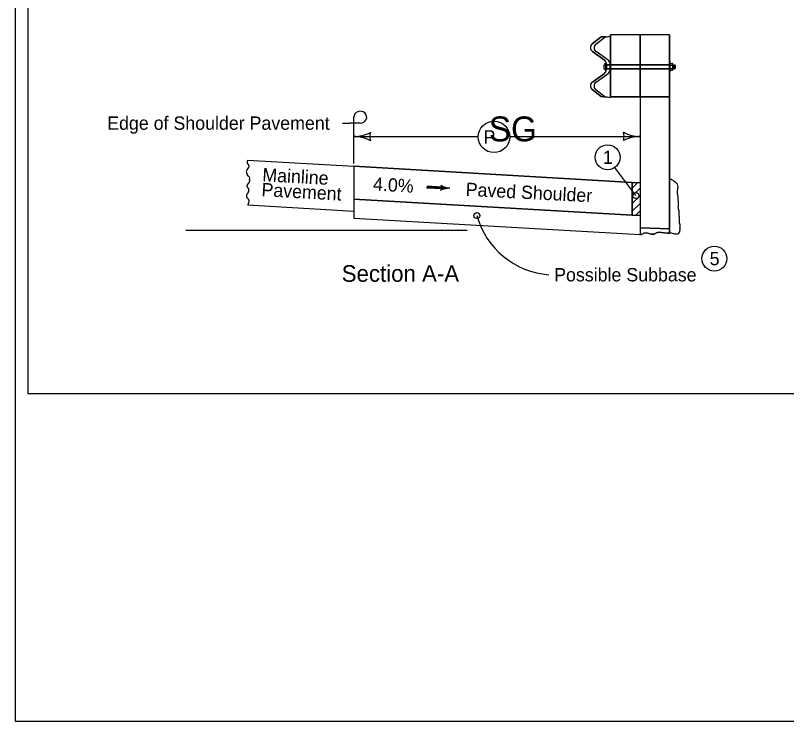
# Model space of a CAD drawing. Extents: x 9538 to 81668, y 7600 to 11751.
# Drawn here: x 10133 to 11060, y 7924 to 8774 of the extents above; entities that cross this region are included whole.
import ezdxf

# ---------------------------------------------------------------- set-up
doc = ezdxf.new("R2010")
doc.units = 0
for name, color, linetype in [('Default', 7, 'Continuous'), ('DsnShtMinorGrid13', 7, 'Continuous'), ('DsnShtMinorGrid14', 7, 'Continuous'), ('dsnStdCells', 7, 'Continuous'), ('dsnStdDimension', 7, 'Continuous'), ('dsnStdNameDate', 7, 'Continuous'), ('dsnStdNote', 7, 'Continuous'), ('dsnStdShading', 7, 'Continuous'), ('dsnStdTable', 7, 'Continuous')]:
    doc.layers.add(name, color=color, linetype=linetype)

msp = doc.modelspace()

# ---------------------------------------------------------------- linework, layer by layer
at = {"layer": 'Default'}
msp.add_lwpolyline([(10132.52, 9944.02), (13267.53, 9944.02), (13267.53, 7924.02), (10132.52, 7924.02)], close=True, dxfattribs=at)
at = {"layer": 'DsnShtMinorGrid13'}
for centre, radius in [((10844.79, 8603.28), 15), ((10878.91, 8557.17), 3.58), ((10973.37, 8481.26), 15)]:
    msp.add_circle(centre, radius, dxfattribs=at)
at = {"layer": 'DsnShtMinorGrid14'}
msp.add_circle((10687.61, 8533.07), 3.54, dxfattribs=at)
at = {"layer": 'dsnStdCells'}
for p, q in [((10826.55, 8730.73), (10841.06, 8720.31)), ((10841.06, 8704.24), (10826.55, 8693.82))]:
    msp.add_line(p, q, dxfattribs=at)
for points in [[(10830.8, 8739.63), (10830.79, 8739.62), (10841.57, 8748.02), (10843.45, 8748.36), (10837.12, 8748.24), (10826.36, 8739.85)], [(10883.85, 8714.93), (10883.85, 8750.61), (10848.3, 8750.61), (10848.3, 8714.93), (10848.3, 8714.93), (10883.85, 8714.93)], [(10919.39, 8714.93), (10919.39, 8718.93), (10919.39, 8750.61), (10883.85, 8750.61), (10883.85, 8714.93), (10919.39, 8714.93)], [(10845.51, 8720.09), (10845.54, 8720.07), (10830.97, 8730.53), (10831, 8730.51)], [(10843.46, 8715.68), (10843.46, 8714.6), (10847.9, 8714.6), (10847.9, 8715.46), (10847.9, 8715.46)], [(10848.3, 8714.6), (10848.3, 8709.93), (10848.3, 8709.93), (10883.85, 8709.93), (10883.85, 8714.6), (10848.3, 8714.6), (10848.3, 8714.6)], [(10919.39, 8709.93), (10919.39, 8714.6), (10883.85, 8714.6), (10883.85, 8709.93), (10919.39, 8709.93)], [(10831, 8693.6), (10830.97, 8693.58), (10845.54, 8704.04), (10845.51, 8704.02)], [(10847.9, 8708.65), (10847.9, 8708.65), (10847.9, 8709.93), (10843.46, 8709.93), (10843.46, 8708.87), (10843.46, 8709.93), (10843.46, 8709.93), (10843.46, 8708.87)], [(10848.3, 8709.6), (10848.3, 8675.96), (10883.85, 8675.96), (10883.85, 8709.6), (10848.3, 8709.6)], [(10919.39, 8675.96), (10919.39, 8705.6), (10919.39, 8709.6), (10883.85, 8709.6), (10883.85, 8675.96), (10919.39, 8675.96)], [(10826.36, 8684.7), (10837.12, 8676.31), (10844.23, 8675.62), (10841.57, 8676.09), (10830.79, 8684.5), (10830.8, 8684.48)], [(10919.39, 8517.01), (10919.39, 8675.96), (10883.85, 8675.96), (10883.85, 8572.99), (10883.85, 8566.3), (10883.85, 8566.3), (10883.85, 8566.3), (10883.85, 8557.07), (10883.85, 8557.07), (10883.85, 8557.07), (10883.85, 8547.93), (10883.85, 8547.93), (10883.85, 8547.93), (10883.85, 8541), (10883.85, 8518.17), (10919.39, 8517.01)], [(10919.39, 8517.01), (10883.85, 8518.17), (10883.85, 8510.15), (10885.48, 8510.38), (10888.24, 8511.97), (10891.53, 8512.5), (10897.14, 8510.91), (10900.85, 8510.69), (10903.5, 8512.5), (10906.58, 8513.13), (10912.83, 8512.39), (10917.07, 8511.97), (10919.39, 8511.97), (10919.39, 8517.01)]]:
    msp.add_lwpolyline(points, dxfattribs=at)
msp.add_lwpolyline([(10847.9, 8714.6), (10843.46, 8714.6), (10843.46, 8711.14), (10843.46, 8712.27), (10843.46, 8709.93), (10847.9, 8709.93)], close=True, dxfattribs=at)
for centre, start, end in [((10829.83, 8735.36), 127.75002, 234.69086), ((10834.28, 8735.14), 127.75002, 234.69086), ((10837.78, 8715.68), 0, 54.69099), ((10842.23, 8715.46), 0, 54.69099), ((10837.78, 8708.87), 305.30901, 0), ((10842.23, 8708.65), 305.30901, 0), ((10829.83, 8689.19), 125.30914, 232.24998), ((10834.28, 8688.97), 125.30914, 232.24998)]:
    msp.add_arc(centre, 5.68, start, end, dxfattribs=at)
at = {"layer": 'dsnStdDimension'}
for p, q in [((10539.46, 8628.24), (10689.29, 8628.24)), ((10727.14, 8628.4), (10883.85, 8628.4))]:
    msp.add_line(p, q, dxfattribs=at)
msp.add_circle((10708.21, 8627.84), 18.93, dxfattribs=at)
for centre, radius, start, end in [((10539.46, 8670.74), 42.5, 270, 298.07249), ((10539.46, 8585.74), 42.5, 61.92751, 90), ((10575.09, 8628.24), 16.42, 162.26665, 197.73335), ((10848.21, 8628.4), 16.42, 342.26665, 17.73335), ((10883.85, 8670.9), 42.5, 241.92751, 270), ((10883.85, 8585.9), 42.5, 90, 118.07249), ((10781.77, 8559.36), 97.76, 195.59781, 265.55799)]:
    msp.add_arc(centre, radius, start, end, dxfattribs=at)
at = {"layer": 'dsnStdNameDate'}
for p, q in [((10874.59, 8572.99), (10539.46, 8592.48)), ((10539.46, 8592.48), (10539.46, 8552.88)), ((10878.91, 8557.17), (10853.53, 8591.09)), ((10874.59, 8533.56), (10874.59, 8572.99)), ((10539.46, 8552.88), (10874.59, 8533.56))]:
    msp.add_line(p, q, dxfattribs=at)
at = {"layer": 'dsnStdNote'}
for p, q in [((10539.46, 8631.56), (10539.46, 8652.42)), ((10526.09, 8644.41), (10534.77, 8644.41)), ((10547.27, 8644.41), (10534.77, 8644.41)), ((10539.46, 8595.62), (10539.46, 8631.56)), ((10645.84, 8566.52), (10627.63, 8567.57)), ((10645.74, 8565.58), (10645.74, 8565.58)), ((10645.85, 8567.53), (10645.85, 8567.53))]:
    msp.add_line(p, q, dxfattribs=at)
for points in [[(10645.87, 8567.46), (10627.7, 8568.51), (10627.57, 8566.63), (10645.74, 8565.58), (10645.79, 8567.19), (10627.92, 8568.29), (10627.86, 8566.79), (10645.35, 8565.84), (10645.48, 8566.96), (10628.15, 8568.02), (10628.13, 8567.02), (10645.14, 8566.04), (10645.23, 8566.75), (10628.34, 8567.8), (10628.33, 8567.24), (10644.93, 8566.31)], [(10645.46, 8568.72), (10646.16, 8567.55), (10646.13, 8565.9), (10645.38, 8564.51), (10648.13, 8565.37), (10651.33, 8566.02), (10652.23, 8566.16), (10649.98, 8566.7), (10646.75, 8567.93), (10645.81, 8568.47), (10645.93, 8564.95), (10650.88, 8566.17), (10646.24, 8567.75), (10646.25, 8565.33), (10649.65, 8566.26), (10646.65, 8567.12), (10646.42, 8565.74), (10648.58, 8566.24), (10646.99, 8566.75), (10646.86, 8566.09), (10647.64, 8566.25)]]:
    msp.add_lwpolyline(points, dxfattribs=at)
for centre, major_axis, start_param, end_param in [((10547.27, 8651.54), (-7.81, 0), 1.570796, 6.283185), ((10642.07, 8566.74), (3.88, 0), 5.202895, 7.237436), ((10654.34, 8545.74), (22.17, 0), 1.537172, 2.061295), ((10657.13, 8586.16), (-22.17, 0), 0.954258, 1.478381)]:
    msp.add_ellipse(centre, major_axis=major_axis, ratio=0.913811, start_param=start_param, end_param=end_param, dxfattribs=at)
at = {"layer": 'dsnStdShading'}
for p, q in [((10147.52, 9929.02), (10147.52, 8319.02)), ((10147.52, 8319.02), (13243.21, 8319.02))]:
    msp.add_line(p, q, dxfattribs=at)
at = {"layer": 'dsnStdTable'}
for p, q in [((10826.36, 8739.85), (10837.12, 8748.24)), ((10830.79, 8739.62), (10841.57, 8748.02)), ((10837.12, 8748.24), (10843.45, 8748.36)), ((10841.57, 8748.02), (10847.9, 8749.14)), ((10919.39, 8750.61), (10848.3, 8750.61)), ((10848.3, 8675.96), (10848.3, 8750.61)), ((10883.85, 8675.96), (10883.85, 8750.61)), ((10919.39, 8750.61), (10919.39, 8511.97)), ((10841.06, 8720.31), (10826.55, 8730.73)), ((10845.54, 8720.07), (10830.97, 8730.53)), ((10842.69, 8708.21), (10842.69, 8716.29)), ((10842.69, 8714.6), (10848.11, 8714.6)), ((10843.46, 8708.87), (10843.46, 8715.68)), ((10843.46, 8708.87), (10843.46, 8712.27)), ((10843.46, 8712.27), (10843.46, 8708.87)), ((10843.63, 8714.6), (10848.3, 8714.6)), ((10847.9, 8712.06), (10847.9, 8715.46)), ((10847.9, 8708.65), (10847.9, 8712.06)), ((10847.9, 8712.06), (10847.9, 8708.65)), ((10848.3, 8714.93), (10919.39, 8714.93)), ((10848.3, 8714.6), (10919.39, 8714.6)), ((10919.39, 8718.9), (10920.07, 8718.9)), ((10920.07, 8705.57), (10920.07, 8718.9)), ((10920.07, 8716.28), (10923.04, 8716.28)), ((10920.07, 8714.26), (10923.04, 8714.26)), ((10923.41, 8709.21), (10923.41, 8715.27)), ((10923.41, 8714.57), (10925.78, 8714.57)), ((10924.3, 8714.57), (10924.3, 8709.9)), ((10925.04, 8714.57), (10925.04, 8709.9)), ((10925.78, 8714.57), (10926.22, 8714.04)), ((10925.78, 8714.57), (10925.78, 8709.9)), ((10926.22, 8710.44), (10925.78, 8709.9)), ((10926.22, 8714.04), (10926.22, 8710.44)), ((10826.55, 8693.82), (10841.06, 8704.24)), ((10830.97, 8693.58), (10845.54, 8704.04)), ((10842.69, 8709.93), (10848.3, 8709.93)), ((10848.29, 8709.6), (10919.39, 8709.6)), ((10848.3, 8709.93), (10919.39, 8709.93)), ((10919.39, 8705.57), (10920.07, 8705.57)), ((10920.07, 8710.22), (10923.04, 8710.22)), ((10920.07, 8708.2), (10923.04, 8708.2)), ((10923.41, 8709.9), (10925.78, 8709.9)), ((10837.12, 8676.31), (10826.36, 8684.7)), ((10841.57, 8676.09), (10830.79, 8684.5)), ((10844.23, 8675.62), (10837.12, 8676.31)), ((10847.9, 8674.97), (10841.57, 8676.09)), ((10883.85, 8675.96), (10848.3, 8675.96)), ((10883.85, 8675.96), (10883.85, 8509.43)), ((10411.84, 8599.9), (10539.46, 8592.48)), ((10539.46, 8592.48), (10539.46, 8538.47)), ((10539.46, 8592.48), (10874.59, 8572.99)), ((10874.59, 8566.25), (10881.34, 8572.99)), ((10874.59, 8566.25), (10881.34, 8572.99)), ((10874.59, 8566.25), (10881.34, 8572.99)), ((10874.59, 8566.25), (10881.34, 8572.99)), ((10874.59, 8572.99), (10883.83, 8572.99)), ((10874.59, 8572.99), (10874.59, 8533.56)), ((10874.59, 8557.06), (10883.83, 8566.3)), ((10874.59, 8557.06), (10883.83, 8566.3)), ((10874.59, 8557.06), (10883.83, 8566.3)), ((10874.59, 8557.06), (10883.83, 8566.3)), ((10929.44, 8566.23), (10929.44, 8566.23)), ((10874.59, 8533.56), (10539.46, 8552.88)), ((10874.59, 8547.84), (10883.83, 8557.07)), ((10874.59, 8547.84), (10883.83, 8557.07)), ((10874.59, 8547.84), (10883.83, 8557.07)), ((10874.59, 8547.84), (10883.83, 8557.07)), ((10412.02, 8545.88), (10539.46, 8538.47)), ((10874.59, 8538.61), (10883.83, 8547.84)), ((10539.46, 8538.47), (10539.46, 8530.05)), ((10878.69, 8533.56), (10883.83, 8538.7)), ((10539.46, 8530.05), (10883.85, 8510.19)), ((10874.59, 8533.56), (10883.83, 8533.56)), ((10337.4, 8515.64), (10675.9, 8515.64))]:
    msp.add_line(p, q, dxfattribs=at)
for points in [[(10923.39, 8709.53), (10923.35, 8709.8), (10923.3, 8709.97), (10923.21, 8710.13), (10923.09, 8710.22), (10923.17, 8710.32), (10923.26, 8710.54), (10923.31, 8710.85), (10923.39, 8711.6), (10923.39, 8709.53), (10923.37, 8709.67), (10923.33, 8709.88), (10923.25, 8710.09), (10923.14, 8710.21), (10923.17, 8710.29), (10923.23, 8710.44), (10923.34, 8710.94), (10923.38, 8711.32), (10923.37, 8709.72), (10923.35, 8709.84), (10923.3, 8710), (10923.17, 8710.21), (10923.23, 8710.38), (10923.3, 8710.71), (10923.36, 8711.04), (10923.35, 8709.87), (10923.31, 8710), (10923.2, 8710.2), (10923.24, 8710.41), (10923.3, 8710.67), (10923.34, 8710.84), (10923.33, 8709.98), (10923.27, 8710.09), (10923.23, 8710.2), (10923.31, 8710.66), (10923.31, 8710.06), (10923.24, 8710.2), (10923.29, 8710.49), (10923.29, 8710.14), (10923.26, 8710.21), (10923.27, 8710.31), (10923.27, 8710.23)], [(10923.1, 8714.26), (10923.18, 8714.3), (10923.25, 8714.41), (10923.33, 8714.63), (10923.39, 8714.91), (10923.39, 8712.97), (10923.33, 8713.48), (10923.28, 8713.85), (10923.16, 8714.17), (10923.11, 8714.26), (10923.16, 8714.27), (10923.27, 8714.41), (10923.35, 8714.64), (10923.37, 8714.79), (10923.38, 8713.26), (10923.3, 8713.75), (10923.25, 8714.01), (10923.14, 8714.24), (10923.17, 8714.25), (10923.31, 8714.47), (10923.35, 8714.62), (10923.36, 8713.51), (10923.17, 8714.23), (10923.33, 8714.5), (10923.34, 8713.65), (10923.19, 8714.21), (10923.31, 8714.43), (10923.32, 8713.79), (10923.21, 8714.2), (10923.3, 8714.37), (10923.3, 8713.96), (10923.23, 8714.18), (10923.28, 8714.3), (10923.28, 8714.09), (10923.25, 8714.17), (10923.26, 8714.21)], [(10929.91, 8542.38), (10929.85, 8542.11), (10929.85, 8541.92), (10929.85, 8541.72), (10929.85, 8541.53), (10929.85, 8541.33), (10929.85, 8541.14), (10929.85, 8540.84), (10929.85, 8540.65), (10929.95, 8540.35), (10930.05, 8540.06), (10930.24, 8539.87), (10930.24, 8539.67), (10930.34, 8539.47), (10930.34, 8539.28), (10930.34, 8539.08), (10930.44, 8538.99), (10930.44, 8538.79), (10930.44, 8538.59), (10930.44, 8538.4), (10930.44, 8538.2), (10930.44, 8538.01), (10930.44, 8537.72), (10930.44, 8537.42), (10930.44, 8537.23), (10930.44, 8536.93), (10930.44, 8536.74), (10930.44, 8536.54), (10930.54, 8536.45), (10930.54, 8536.25), (10930.54, 8536.05), (10930.54, 8535.86), (10930.54, 8535.66), (10930.54, 8535.47), (10930.54, 8535.27), (10930.54, 8535.08), (10930.54, 8534.88), (10930.54, 8534.69), (10930.54, 8534.49), (10930.54, 8534.3), (10930.54, 8534.1), (10930.54, 8533.91), (10930.54, 8533.71), (10930.54, 8533.51), (10930.54, 8533.32), (10930.54, 8533.12), (10930.54, 8532.93), (10930.64, 8532.83), (10930.64, 8532.63), (10930.64, 8532.44), (10930.73, 8532.34), (10930.73, 8532.15), (10930.73, 8531.95), (10930.83, 8531.85), (10930.83, 8531.66), (10930.83, 8531.46), (10930.83, 8531.27), (10930.83, 8530.97), (10930.93, 8530.68), (10930.93, 8530.49), (10930.93, 8530.29), (10930.93, 8530.09), (10930.93, 8529.9), (10930.93, 8529.7), (10930.93, 8529.51), (10930.93, 8529.31), (10930.93, 8529.12), (10930.93, 8528.92), (10930.93, 8528.73), (10930.93, 8528.53), (10930.93, 8528.34), (10930.93, 8528.14), (10930.93, 8527.95), (10930.93, 8527.75), (10930.93, 8527.55), (10930.93, 8527.36), (10930.93, 8527.16), (10930.93, 8526.97), (10930.93, 8526.77), (10930.93, 8526.58), (10930.93, 8526.38), (10930.93, 8526.19), (10930.93, 8525.99), (10930.93, 8525.8), (10930.93, 8525.6), (10930.93, 8525.4), (10930.93, 8525.21), (10930.93, 8525.01), (10931.03, 8524.92), (10931.03, 8524.62), (10931.03, 8524.43), (10931.12, 8524.23), (10931.22, 8523.94), (10931.22, 8523.74), (10931.32, 8523.65), (10931.32, 8523.45), (10931.42, 8523.35), (10931.52, 8523.26), (10931.52, 8523.06), (10931.52, 8522.86), (10931.52, 8522.67), (10931.61, 8522.57), (10931.61, 8522.38), (10931.61, 8522.18), (10931.61, 8521.99), (10931.61, 8521.79), (10931.61, 8521.59), (10931.61, 8521.4), (10931.61, 8521.2), (10931.61, 8521.01), (10931.61, 8520.81), (10931.61, 8520.62), (10931.61, 8520.42), (10931.61, 8520.23), (10931.61, 8520.03), (10931.61, 8519.84), (10931.61, 8519.64), (10931.61, 8519.44), (10931.61, 8519.25), (10931.61, 8519.05), (10931.61, 8518.86), (10931.61, 8518.66), (10931.61, 8518.47), (10931.61, 8518.27), (10931.61, 8518.08), (10931.61, 8517.88), (10931.61, 8517.69), (10931.61, 8517.69), (10931.61, 8517.98), (10931.61, 8518.17), (10931.61, 8518.37), (10931.61, 8518.17), (10931.61, 8517.98), (10931.61, 8517.78), (10931.61, 8517.59), (10931.61, 8517.39), (10931.61, 8517.2), (10931.61, 8517), (10931.61, 8516.81), (10931.61, 8516.61), (10931.61, 8516.42), (10931.61, 8516.22), (10931.61, 8516.03), (10931.61, 8515.83), (10931.61, 8515.63), (10931.61, 8515.44), (10931.52, 8515.34), (10931.52, 8515.15), (10931.52, 8514.95), (10931.52, 8514.76), (10931.52, 8514.56), (10931.52, 8514.36), (10931.52, 8514.17), (10931.52, 8513.97), (10931.52, 8513.78), (10931.52, 8513.58), (10931.52, 8513.39), (10931.42, 8513.29), (10931.32, 8513.09), (10931.22, 8513), (10931.12, 8512.9), (10931.03, 8512.8), (10930.83, 8512.7), (10930.64, 8512.7), (10930.54, 8512.61), (10930.44, 8512.51), (10930.34, 8512.41), (10930.15, 8512.31), (10930.05, 8512.21), (10930.05, 8512.02), (10929.95, 8511.92), (10929.95, 8511.73), (10929.95, 8511.53), (10929.95, 8511.34), (10929.95, 8511.14), (10929.95, 8511.04), (10929.95, 8511.24)], [(10929.91, 8510.92), (10925.76, 8510.8), (10921.63, 8511.97), (10917.07, 8511.97), (10912.83, 8512.39), (10906.58, 8513.13), (10903.5, 8512.5), (10900.85, 8510.69), (10897.14, 8510.91), (10891.53, 8512.5), (10888.24, 8511.97), (10885.48, 8510.38), (10883.85, 8510.15)]]:
    msp.add_lwpolyline(points, dxfattribs=at)
for centre, radius, start, end in [((10829.83, 8735.36), 5.68, 127.75002, 234.69086), ((10834.28, 8735.14), 5.68, 127.75002, 234.69086), ((10837.78, 8715.68), 5.68, 360, 54.69099), ((10842.23, 8715.46), 5.68, 360, 54.69099), ((10844.76, 8712.26), 4.54, 117.20289, 242.8461), ((10837.78, 8708.87), 5.68, 305.30901, 0), ((10842.23, 8708.65), 5.68, 305.30901, 0), ((10829.83, 8689.19), 5.68, 125.30914, 232.24998), ((10834.28, 8688.97), 5.68, 125.30914, 232.24998)]:
    msp.add_arc(centre, radius, start, end, dxfattribs=at)
for centre in [(10923.04, 8715.27), (10923.04, 8709.21)]:
    msp.add_ellipse(centre, major_axis=(0, -1.01), ratio=0.362258, start_param=6.283156, end_param=9.424748, dxfattribs=at)
for points in [[(10411.84, 8599.9), (10411.34, 8596.3), (10412.38, 8594.79), (10413.24, 8592.5), (10412.64, 8590.44), (10410.73, 8588.06), (10410.21, 8586.16), (10410.73, 8583.87), (10411.6, 8581.49), (10412.64, 8580.78), (10414.02, 8578.24), (10414.01, 8577.4)], [(10412.05, 8560.29), (10412.26, 8560.54), (10412.46, 8560.8), (10412.81, 8561.36), (10413.09, 8561.95), (10413.21, 8562.26), (10413.31, 8562.57), (10413.44, 8563.19), (10413.49, 8563.81), (10413.44, 8564.4), (10413.39, 8564.68), (10413.35, 8564.81), (10413.3, 8564.94), (10413.09, 8565.32), (10412.81, 8565.68), (10412.51, 8566.05), (10412.26, 8566.45), (10412.12, 8566.73), (10411.98, 8567.01), (10411.72, 8567.59), (10411.52, 8568.15), (10411.45, 8568.45), (10411.39, 8568.74), (10411.38, 8568.87), (10411.38, 8569), (10411.53, 8569.77), (10411.74, 8570.29), (10412, 8570.8), (10412.45, 8571.44), (10412.96, 8571.98), (10413.48, 8572.53), (10413.71, 8572.84), (10413.91, 8573.18), (10414.12, 8573.65), (10414.27, 8574.13), (10414.37, 8574.6), (10414.41, 8574.84), (10414.42, 8574.96), (10414.43, 8575.08), (10414.38, 8575.59), (10414.23, 8576.1), (10414.18, 8576.23), (10414.12, 8576.35), (10414.08, 8576.48), (10414.05, 8576.61), (10414.01, 8577.4)], [(10929.91, 8542.38), (10930.23, 8545.29), (10930.01, 8550.15), (10929.57, 8555.9), (10928.91, 8560.33), (10929.13, 8563.64), (10929.57, 8567.84), (10928.91, 8570.94), (10926.7, 8572.93), (10924.71, 8574.7), (10922.49, 8575.81), (10920.28, 8577.13), (10919.4, 8577.8)], [(10412.05, 8560.29), (10411.84, 8560.06), (10411.59, 8559.82), (10411.35, 8559.58), (10411.17, 8559.31), (10411.03, 8559.03), (10410.89, 8558.74), (10410.63, 8558.17), (10410.52, 8557.89), (10410.43, 8557.6), (10410.35, 8557.31), (10410.33, 8557.16), (10410.3, 8557.01), (10410.31, 8556.5), (10410.44, 8555.98), (10410.65, 8555.46), (10410.91, 8554.95), (10411.36, 8554.32), (10411.87, 8553.77), (10412.39, 8553.22), (10412.62, 8552.92), (10412.82, 8552.58), (10413.22, 8551.63), (10413.33, 8551.16), (10413.34, 8550.68), (10413.3, 8550.39), (10413.26, 8550.1), (10413.2, 8549.81), (10413.13, 8549.53), (10412.82, 8548.38), (10412.64, 8547.77), (10412.44, 8547.17), (10412.22, 8546.58), (10412.09, 8546.29), (10411.95, 8546.01), (10411.87, 8545.89)]]:
    msp.add_spline(points, degree=3, dxfattribs=at)

# ---------------------------------------------------------------- texts
at = {"layer": 'DsnShtMinorGrid13'}
for s, p in [('1', (10839.16, 8595.28)), ('5', (10967.61, 8473.26))]:
    msp.add_text(s, height=16, dxfattribs=at).set_placement(p)
at = {"layer": 'dsnStdDimension'}
for s, height, p in [('SG', 30, (10701.93, 8622.4)), ('P', 16, (10695.5, 8619.84))]:
    msp.add_text(s, height=height, dxfattribs=at).set_placement(p)
at = {"layer": 'dsnStdNote'}
for s, height, p in [('Edge of Shoulder Pavement', 16, (10242.92, 8636.41)), ('Section A-A', 20, (10525.03, 8453.39)), ('Possible Subbase', 16, (10780.56, 8453.89))]:
    msp.add_text(s, height=height, dxfattribs=at).set_placement(p)
for s, rotation, p in [('Mainline', 356.73462, (10429.21, 8574.55)), ('Pavement', 356.73462, (10428.19, 8556.58)), ('4.0%', 356.69917, (10562.38, 8563.35)), ('Paved Shoulder ', 357.0678, (10673.85, 8556.89))]:
    msp.add_text(s, height=16, rotation=rotation, dxfattribs=at).set_placement(p)

doc.saveas('drawing.dxf')
